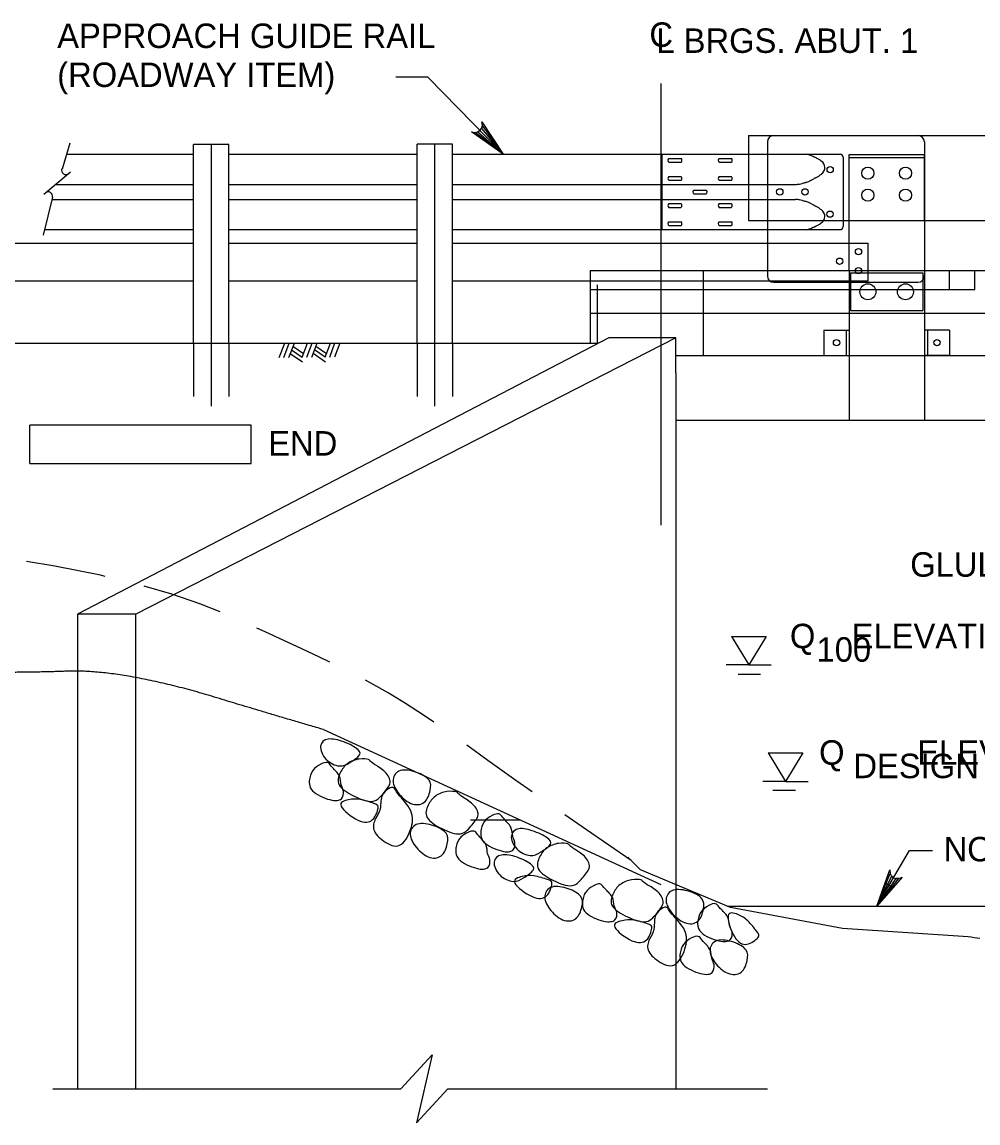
# Model space of a CAD drawing. Extents: x 638268 to 640277, y 295465 to 298435.
# Drawn here: x 638488.1 to 638605.4, y 297978 to 298112.9 of the extents above; entities that cross this region are included whole.
import ezdxf

# ---------------------------------------------------------------- set-up
doc = ezdxf.new("R2010")
doc.units = 0
for name, color, linetype in [('2', 7, 'Continuous'), ('3', 7, 'Continuous'), ('4', 7, 'Continuous'), ('52', 7, 'Continuous'), ('8', 7, 'Continuous'), ('Level 25', 7, 'Continuous')]:
    doc.layers.add(name, color=color, linetype=linetype)

msp = doc.modelspace()

# ---------------------------------------------------------------- linework, layer by layer
at = {"layer": '2'}
for p, q in [((638577.23, 298099.02), (638577.23, 298096.71)), ((638577.23, 298099.02), (638750.23, 298099.02)), ((638493.6, 298096.72), (638509.18, 298096.72)), ((638513.5, 298096.72), (638536.57, 298096.72)), ((638540.9, 298096.72), (638566.58, 298096.72)), ((638566.58, 298096.72), (638566.58, 298087.48)), ((638566.64, 298096.72), (638577.23, 298096.72)), ((638577.23, 298096.72), (638588.44, 298096.72)), ((638577.23, 298096.7), (638577.23, 298088.62)), ((638589.55, 298096.7), (638598.78, 298096.7)), ((638589.55, 298082.46), (638589.55, 298096.7)), ((638598.78, 298088.62), (638598.78, 298096.7)), ((638567.45, 298096.21), (638568.92, 298096.21)), ((638567.45, 298095.75), (638568.92, 298095.75)), ((638573.62, 298096.21), (638575.1, 298096.21)), ((638573.62, 298095.75), (638575.1, 298095.75)), ((638588.81, 298096.35), (638588.81, 298087.85)), ((638589.55, 298096.32), (638598.78, 298096.32)), ((638567.45, 298093.99), (638568.92, 298093.99)), ((638573.62, 298093.99), (638575.1, 298093.99)), ((638492.25, 298093.02), (638509.18, 298093.02)), ((638513.5, 298093.02), (638536.57, 298093.02)), ((638540.9, 298093.02), (638577.23, 298093.02)), ((638567.45, 298093.53), (638568.92, 298093.53)), ((638570.53, 298092.33), (638572.01, 298092.33)), ((638573.62, 298093.53), (638575.1, 298093.53)), ((638577.23, 298093.02), (638582.98, 298093.02)), ((638491.81, 298091.18), (638509.18, 298091.18)), ((638513.5, 298091.18), (638536.57, 298091.18)), ((638540.9, 298091.18), (638577.23, 298091.18)), ((638570.53, 298091.87), (638572.01, 298091.87)), ((638577.23, 298091.18), (638582.98, 298091.18)), ((638567.45, 298090.67), (638568.92, 298090.67)), ((638567.45, 298090.2), (638568.92, 298090.2)), ((638573.62, 298090.67), (638575.1, 298090.67)), ((638573.62, 298090.2), (638575.1, 298090.2)), ((638567.45, 298088.45), (638568.92, 298088.45)), ((638573.62, 298088.45), (638575.1, 298088.45)), ((638577.23, 298088.62), (638579.54, 298088.62)), ((638579.54, 298088.62), (638589.55, 298088.62)), ((638589.55, 298088.62), (638598.78, 298088.62)), ((638598.78, 298088.62), (638598.78, 298082.46)), ((638598.78, 298088.62), (638637.2, 298088.62)), ((638490.88, 298087.48), (638509.18, 298087.48)), ((638513.5, 298087.48), (638536.57, 298087.48)), ((638540.9, 298087.48), (638579.54, 298087.48)), ((638567.45, 298087.99), (638568.92, 298087.99)), ((638573.62, 298087.99), (638575.1, 298087.99)), ((638579.54, 298087.48), (638588.44, 298087.48)), ((638486.95, 298085.82), (638509.18, 298085.82)), ((638513.5, 298085.82), (638536.57, 298085.82)), ((638540.9, 298085.82), (638579.54, 298085.82)), ((638579.54, 298085.82), (638591.89, 298085.82)), ((638591.89, 298081.2), (638591.89, 298085.82)), ((638557.8, 298082.46), (638589.55, 298082.46)), ((638557.8, 298082.46), (638557.8, 298073.51)), ((638571.65, 298082.46), (638571.65, 298072.07)), ((638579.54, 298082.46), (638579.54, 298081.8)), ((638589.55, 298082.46), (638598.78, 298082.46)), ((638589.55, 298082.46), (638589.55, 298064.14)), ((638589.71, 298082.18), (638589.71, 298077.56)), ((638589.71, 298082.18), (638598.59, 298082.18)), ((638598.59, 298082.18), (638598.59, 298077.56)), ((638598.78, 298082.46), (638637.2, 298082.46)), ((638598.78, 298082.46), (638598.78, 298064.14)), ((638601.86, 298080.15), (638601.86, 298082.46)), ((638604.95, 298080.15), (638604.95, 298082.46)), ((638485.55, 298081.2), (638509.18, 298081.2)), ((638513.5, 298081.2), (638536.57, 298081.2)), ((638540.9, 298081.2), (638557.8, 298081.2)), ((638557.8, 298081.2), (638591.89, 298081.2)), ((638557.8, 298080.15), (638604.95, 298080.15)), ((638589.71, 298077.56), (638598.59, 298077.56)), ((638557.8, 298077.26), (638589.55, 298077.26)), ((638589.55, 298077.26), (638598.78, 298077.26)), ((638598.78, 298077.26), (638614.94, 298077.26)), ((638586.45, 298075.16), (638589.55, 298075.16)), ((638586.45, 298075.16), (638586.45, 298072.07)), ((638589.18, 298075.16), (638589.18, 298072.07)), ((638589.55, 298075.16), (638589.55, 298072.07)), ((638601.87, 298075.16), (638598.78, 298075.16)), ((638598.78, 298075.16), (638598.78, 298072.07)), ((638599.15, 298075.16), (638599.15, 298072.07)), ((638601.87, 298075.16), (638601.87, 298072.07)), ((638586.45, 298072.07), (638589.55, 298072.07)), ((638589.55, 298072.07), (638598.78, 298072.07)), ((638601.87, 298072.07), (638598.78, 298072.07)), ((638598.78, 298072.07), (638637.2, 298072.07)), ((638601.87, 298072.07), (638598.78, 298072.07))]:
    msp.add_line(p, q, dxfattribs=at)
for centre, radius in [((638587.23, 298094.84), 0.385), ((638591.85, 298094.4), 0.748), ((638596.47, 298094.4), 0.748), ((638581.05, 298092.11), 0.385), ((638584.13, 298092.11), 0.385), ((638591.85, 298091.7), 0.748), ((638596.47, 298091.7), 0.748), ((638587.21, 298089.38), 0.385), ((638590.7, 298084.77), 0.385), ((638588.39, 298083.61), 0.385), ((638590.7, 298082.46), 0.385), ((638591.85, 298079.86), 0.978), ((638596.46, 298079.86), 0.978), ((638588.01, 298073.62), 0.385), ((638600.32, 298073.62), 0.385)]:
    msp.add_circle(centre, radius, dxfattribs=at)
for centre, radius, start, end in [((638581.4, 298086.99), 10.17, 71.5066, 72.9766), ((638584.03, 298094.85), 1.88, 68.0907, 71.5066), ((638560.58, 298036.55), 64.73, 67.6851, 68.0907), ((638582.91, 298090.94), 5.93, 66.3453, 67.6851), ((638584.32, 298094.16), 2.42, 63.4251, 66.3453), ((638588.44, 298096.35), 0.369, 0, 90), ((638567.58, 298095.98), 0.269, 120.8559, 239.1441), ((638568.79, 298095.98), 0.269, 300.8559, 59.1441), ((638573.76, 298095.98), 0.269, 120.8559, 239.1441), ((638574.96, 298095.98), 0.269, 300.8559, 59.1441), ((638571.17, 298067.88), 31.8, 62.6202, 63.4251), ((638585.36, 298095.27), 0.955, 54.6771, 62.6202), ((638583.36, 298092.45), 4.42, 50.9849, 54.6771), ((638585.67, 298095.09), 0.916, 301.3851, 59.6468), ((638567.58, 298093.76), 0.269, 120.8559, 239.1441), ((638568.79, 298093.76), 0.269, 300.8559, 59.1441), ((638573.76, 298093.76), 0.269, 120.8559, 239.1441), ((638574.96, 298093.76), 0.269, 300.8559, 59.1441), ((638640.28, 297992.66), 115.08, 118.565, 118.7501), ((638645.68, 297982.76), 126.36, 118.4725, 118.565), ((638398.16, 298439.15), 392.83, 298.4725, 298.525), ((638585.23, 298094.96), 1.09, 298.525, 306.8818), ((638582.92, 298098.04), 4.94, 306.8818, 310.7993), ((638570.66, 298092.1), 0.269, 120.8559, 239.1441), ((638571.87, 298092.1), 0.269, 300.8559, 59.1441), ((638582.75, 298098.05), 5.03, 272.6429, 278.367), ((638583.16, 298095.21), 2.16, 278.367, 287.1115), ((638556.74, 298181.03), 91.96, 287.1115, 287.3611), ((638583.24, 298096.26), 3.14, 287.3611, 288.7111), ((638578.42, 298110.5), 18.18, 288.7111, 290.2329), ((638584.49, 298094.05), 0.644, 290.2329, 298.3215), ((638574.61, 298112.37), 21.45, 298.3215, 298.7501), ((638582.75, 298086.15), 5.03, 81.633, 87.3571), ((638583.16, 298088.99), 2.16, 72.8885, 81.633), ((638556.74, 298003.16), 91.96, 72.6389, 72.8885), ((638567.58, 298090.44), 0.269, 120.8559, 239.1441), ((638568.79, 298090.44), 0.269, 300.8559, 59.1441), ((638573.76, 298090.44), 0.269, 120.8559, 239.1441), ((638574.96, 298090.44), 0.269, 300.8559, 59.1441), ((638583.24, 298087.94), 3.14, 71.2889, 72.6389), ((638578.42, 298073.7), 18.18, 69.7671, 71.2889), ((638584.49, 298090.15), 0.644, 61.6785, 69.7671), ((638574.61, 298071.83), 21.45, 61.2499, 61.6785), ((638640.28, 298191.53), 115.08, 241.2499, 241.435), ((638645.68, 298201.44), 126.36, 241.435, 241.5275), ((638398.16, 297745.04), 392.83, 61.475, 61.5275), ((638585.23, 298089.23), 1.09, 53.1182, 61.475), ((638582.92, 298086.15), 4.94, 49.2007, 53.1182), ((638585.67, 298089.11), 0.916, 300.3532, 58.6149), ((638567.58, 298088.22), 0.269, 120.8559, 239.1441), ((638568.79, 298088.22), 0.269, 300.8559, 59.1441), ((638573.76, 298088.22), 0.269, 120.8559, 239.1441), ((638574.96, 298088.22), 0.269, 300.8559, 59.1441), ((638583.36, 298091.75), 4.42, 305.3229, 309.0151), ((638581.4, 298097.2), 10.17, 287.0234, 288.4934), ((638584.03, 298089.35), 1.88, 288.4934, 291.9093), ((638560.58, 298147.65), 64.73, 291.9093, 292.3149), ((638582.91, 298093.26), 5.93, 292.3149, 293.6547), ((638584.32, 298090.04), 2.42, 293.6547, 296.5749), ((638571.17, 298116.32), 31.8, 296.5749, 297.3798), ((638585.36, 298088.93), 0.955, 297.3798, 305.3229), ((638588.44, 298087.85), 0.369, 270, 0)]:
    msp.add_arc(centre, radius, start, end, dxfattribs=at)
at = {"layer": '3'}
for p, q in [((638513.5, 298097.9), (638509.18, 298097.9)), ((638509.18, 298073.51), (638509.18, 298097.9)), ((638511.34, 298097.9), (638511.34, 298065.82)), ((638513.5, 298073.51), (638513.5, 298097.9)), ((638540.9, 298097.98), (638536.57, 298097.98)), ((638536.57, 298073.51), (638536.57, 298097.98)), ((638538.73, 298097.98), (638538.73, 298065.82)), ((638540.9, 298073.51), (638540.9, 298097.98)), ((638494.06, 298094.54), (638490.8, 298091.8)), ((638491.88, 298091.46), (638490.71, 298086.79)), ((638558.69, 298073.51), (638558.69, 298080.72)), ((638558.69, 298073.51), (638480.78, 298073.51)), ((638558.69, 298073.51), (638493.49, 298073.51)), ((638560.07, 298074.23), (638494.94, 298040.35)), ((638568.29, 298074.23), (638502.08, 298040.35)), ((638509.18, 298073.51), (638509.18, 298067.03)), ((638513.5, 298073.51), (638513.5, 298067.03)), ((638520.3, 298073.51), (638519.64, 298071.76)), ((638520.3, 298073.51), (638519.64, 298071.76)), ((638520.85, 298073.52), (638520.18, 298071.76)), ((638520.85, 298073.52), (638520.18, 298071.76)), ((638521.49, 298073.53), (638520.82, 298071.78)), ((638521.49, 298073.53), (638520.82, 298071.78)), ((638523.11, 298073.53), (638522.46, 298071.8)), ((638523.11, 298073.53), (638522.46, 298071.8)), ((638523.66, 298073.54), (638523.01, 298071.81)), ((638523.66, 298073.54), (638523.01, 298071.81)), ((638524.3, 298073.54), (638523.64, 298071.82)), ((638524.3, 298073.54), (638523.64, 298071.82)), ((638525.92, 298073.54), (638525.27, 298071.81)), ((638525.92, 298073.54), (638525.27, 298071.81)), ((638526.47, 298073.55), (638525.82, 298071.82)), ((638526.47, 298073.55), (638525.82, 298071.82)), ((638527.11, 298073.55), (638526.45, 298071.83)), ((638527.11, 298073.55), (638526.45, 298071.83)), ((638536.57, 298073.51), (638536.57, 298067.03)), ((638540.9, 298073.51), (638540.9, 298067.03)), ((638568.29, 298074.23), (638560.07, 298074.23)), ((638568.29, 298069.91), (638568.29, 298074.23)), ((638521.02, 298072.31), (638522.52, 298071.27)), ((638521.02, 298072.31), (638522.52, 298071.27)), ((638521.19, 298072.76), (638522.48, 298071.86)), ((638521.19, 298072.76), (638522.48, 298071.86)), ((638521.35, 298073.19), (638522.64, 298072.29)), ((638521.35, 298073.19), (638522.64, 298072.29)), ((638523.83, 298072.32), (638525.33, 298071.28)), ((638523.83, 298072.32), (638525.33, 298071.28)), ((638524, 298072.77), (638525.29, 298071.88)), ((638524, 298072.77), (638525.29, 298071.88)), ((638524.16, 298073.2), (638525.45, 298072.3)), ((638524.16, 298073.2), (638525.45, 298072.3)), ((638568.29, 298072.07), (638589.55, 298072.07)), ((638568.29, 298069.91), (638568.29, 298007.18)), ((638568.29, 298064.14), (638747.07, 298064.14)), ((638502.08, 298040.35), (638494.94, 298040.35)), ((638494.94, 298040.35), (638494.94, 298033.23)), ((638502.08, 298032.48), (638502.08, 298040.35)), ((638494.94, 298033.23), (638494.94, 297982.13)), ((638502.08, 297982.13), (638502.08, 298032.48)), ((638525.11, 298026.19), (638566.48, 298007.21)), ((638543.13, 298015.12), (638549.23, 298015.12)), ((638568.29, 298007.18), (638568.29, 297982.13)), ((638574.64, 298004.52), (638735.37, 298004.52)), ((638534.59, 297982.13), (638538.43, 297986.3)), ((638538.43, 297986.3), (638536.51, 297977.96)), ((638491.9, 297982.13), (638534.59, 297982.13)), ((638536.51, 297977.96), (638540.35, 297982.13)), ((638540.35, 297982.13), (638579.55, 297982.13))]:
    msp.add_line(p, q, dxfattribs=at)
for centre, radius, start, end in [((638493.5, 298094.77), 0.533, 162.1496, 312.1496), ((638491.36, 298091.58), 0.533, 130.0028, 130.0168), ((638491.36, 298091.58), 0.533, 347.4782, 130.0168), ((638613.42, 298071.3), 71.1, 262.5202, 263.6598)]:
    msp.add_arc(centre, radius, start, end, dxfattribs=at)
for points, degree in [([(638525.11, 298026.19), (638516.58, 298028.68), (638506.65, 298031.73), (638497.12, 298033.48), (638489.77, 298033.19), (638483.62, 298033.19)], 2), ([(638529.39, 298022.92), (638529.15, 298022.66), (638528.28, 298022.11), (638527.18, 298021.46), (638525.2, 298022.4), (638524.44, 298024.33), (638525.52, 298025.24), (638527.55, 298024.8), (638529.73, 298023.65), (638529.63, 298023.18), (638529.39, 298022.92)], 3), ([(638527.27, 298019.42), (638527.34, 298019.12), (638527.64, 298018.75), (638527.49, 298017.53), (638526.14, 298017.36), (638523.25, 298018.61), (638523.34, 298020.36), (638523.86, 298021.47), (638525.12, 298022.17), (638525.77, 298022.2), (638526.07, 298021.59), (638527.24, 298020.56), (638527.2, 298019.72), (638527.27, 298019.42)], 3), ([(638530.8, 298022.36), (638530.86, 298022.28), (638531.19, 298021.99), (638532.78, 298021.07), (638533.57, 298019.64), (638532.57, 298018.59), (638531.37, 298016.96), (638528.79, 298017.96), (638526.57, 298019.38), (638527.12, 298020.98), (638527.91, 298022.1), (638529.51, 298022.71), (638530.86, 298022.5), (638530.75, 298022.45), (638530.8, 298022.36)], 3), ([(638538.03, 298020.02), (638538.31, 298019.65), (638538.27, 298018.81), (638537.65, 298016.99), (638535.8, 298016.85), (638534.06, 298018.47), (638533.36, 298020.11), (638534.33, 298021.45), (638536.6, 298021.04), (638537.75, 298020.39), (638538.03, 298020.02)], 3), ([(638533.71, 298019.05), (638533.85, 298018.96), (638533.96, 298018.51), (638536.22, 298016.2), (638535.97, 298013.99), (638534.57, 298011.4), (638532.38, 298012.41), (638530.96, 298013.92), (638531.44, 298015.29), (638532.19, 298016.31), (638532.04, 298018.14), (638533.13, 298019.05), (638533.57, 298019.14), (638533.71, 298019.05)], 3), ([(638541.58, 298018.38), (638541.64, 298018.3), (638541.97, 298018.01), (638543.55, 298017.09), (638544.35, 298015.66), (638543.35, 298014.61), (638542.14, 298012.98), (638539.56, 298013.98), (638537.34, 298015.39), (638537.89, 298016.99), (638538.68, 298018.12), (638540.28, 298018.73), (638541.63, 298018.52), (638541.52, 298018.46), (638541.58, 298018.38)], 3), ([(638531.26, 298017.14), (638531.68, 298016.99), (638531.99, 298016.89), (638531.28, 298014.83), (638529.56, 298014.66), (638526.44, 298017.12), (638528.28, 298017.65), (638529.47, 298017.75), (638530.84, 298017.28), (638531.26, 298017.14)], 3), ([(638548.3, 298013.13), (638548.36, 298012.83), (638548.66, 298012.46), (638548.51, 298011.24), (638547.17, 298011.07), (638544.27, 298012.32), (638544.37, 298014.07), (638544.88, 298015.17), (638546.14, 298015.88), (638546.8, 298015.91), (638547.09, 298015.3), (638548.27, 298014.26), (638548.23, 298013.43), (638548.3, 298013.13)], 3), ([(638540.14, 298013.47), (638540.41, 298013.1), (638540.38, 298012.26), (638539.75, 298010.44), (638537.91, 298010.3), (638536.16, 298011.92), (638535.46, 298013.56), (638536.43, 298014.9), (638538.7, 298014.49), (638539.86, 298013.84), (638540.14, 298013.47)], 3), ([(638552.78, 298011.94), (638552.54, 298011.68), (638551.67, 298011.13), (638550.57, 298010.48), (638548.59, 298011.42), (638547.83, 298013.35), (638548.91, 298014.25), (638550.94, 298013.81), (638553.12, 298012.67), (638553.02, 298012.19), (638552.78, 298011.94)], 3), ([(638545.23, 298011.01), (638545.3, 298010.71), (638545.6, 298010.34), (638545.45, 298009.11), (638544.1, 298008.95), (638541.21, 298010.2), (638541.3, 298011.95), (638541.81, 298013.05), (638543.07, 298013.76), (638543.73, 298013.79), (638544.03, 298013.18), (638545.2, 298012.15), (638545.16, 298011.31), (638545.23, 298011.01)], 3), ([(638555.25, 298012.02), (638555.3, 298011.94), (638555.63, 298011.65), (638557.22, 298010.74), (638558.01, 298009.3), (638557.01, 298008.25), (638555.81, 298006.62), (638553.23, 298007.63), (638551.01, 298009.04), (638551.56, 298010.64), (638552.35, 298011.76), (638553.95, 298012.37), (638555.3, 298012.16), (638555.19, 298012.11), (638555.25, 298012.02)], 3), ([(638550.7, 298008.82), (638550.46, 298008.55), (638549.61, 298007.98), (638548.52, 298007.31), (638546.52, 298008.19), (638545.71, 298010.1), (638546.77, 298011.03), (638548.8, 298010.65), (638551.01, 298009.56), (638550.93, 298009.08), (638550.7, 298008.82)], 3), ([(638552.56, 298007.81), (638552.98, 298007.67), (638553.29, 298007.58), (638552.64, 298005.5), (638550.92, 298005.28), (638547.74, 298007.67), (638549.56, 298008.24), (638550.75, 298008.38), (638552.14, 298007.94), (638552.56, 298007.81)], 3), ([(638560.76, 298004.57), (638560.84, 298004.28), (638561.15, 298003.92), (638561.03, 298002.69), (638559.69, 298002.49), (638556.77, 298003.66), (638556.81, 298005.42), (638557.3, 298006.53), (638558.54, 298007.27), (638559.19, 298007.32), (638559.51, 298006.71), (638560.71, 298005.71), (638560.69, 298004.87), (638560.76, 298004.57)], 3), ([(638564.22, 298007.61), (638564.28, 298007.52), (638564.62, 298007.25), (638566.23, 298006.37), (638567.06, 298004.96), (638566.08, 298003.88), (638564.92, 298002.22), (638562.32, 298003.16), (638560.06, 298004.51), (638560.57, 298006.13), (638561.33, 298007.27), (638562.92, 298007.92), (638564.27, 298007.75), (638564.16, 298007.69), (638564.22, 298007.61)], 3), ([(638556.63, 298005.76), (638556.91, 298005.39), (638556.87, 298004.55), (638556.24, 298002.72), (638554.4, 298002.59), (638552.65, 298004.21), (638551.96, 298005.84), (638552.92, 298007.18), (638555.2, 298006.77), (638556.35, 298006.13), (638556.63, 298005.76)], 3), ([(638571.51, 298005.45), (638571.8, 298005.09), (638571.78, 298004.25), (638571.2, 298002.41), (638569.36, 298002.23), (638567.57, 298003.8), (638566.83, 298005.42), (638567.77, 298006.78), (638570.05, 298006.43), (638571.22, 298005.82), (638571.51, 298005.45)], 3), ([(638574.9, 298002.16), (638574.98, 298001.86), (638575.29, 298001.5), (638575.17, 298000.27), (638573.83, 298000.07), (638570.9, 298001.24), (638570.95, 298003), (638571.44, 298004.11), (638572.68, 298004.85), (638573.33, 298004.9), (638573.65, 298004.29), (638574.85, 298003.29), (638574.83, 298002.46), (638574.9, 298002.16)], 3), ([(638567.21, 298004.37), (638567.35, 298004.29), (638567.47, 298003.83), (638569.8, 298001.59), (638569.6, 297999.37), (638568.27, 297996.75), (638566.05, 297997.7), (638564.6, 297999.17), (638565.03, 298000.55), (638565.76, 298001.59), (638565.57, 298003.42), (638566.63, 298004.35), (638567.07, 298004.46), (638567.21, 298004.37)], 3), ([(638578.24, 298001.44), (638578.51, 298001.09), (638578.7, 298000.83), (638576.98, 297999.51), (638575.45, 298000.31), (638574.21, 298004.09), (638576.04, 298003.51), (638577.08, 298002.94), (638577.97, 298001.79), (638578.24, 298001.44)], 3), ([(638564.81, 298002.39), (638565.24, 298002.26), (638565.54, 298002.16), (638564.89, 298000.09), (638563.17, 297999.87), (638559.99, 298002.26), (638561.82, 298002.83), (638563, 298002.96), (638564.39, 298002.53), (638564.81, 298002.39)], 3), ([(638572.72, 297998.11), (638572.79, 297997.81), (638573.09, 297997.44), (638572.94, 297996.22), (638571.59, 297996.05), (638568.7, 297997.3), (638568.79, 297999.06), (638569.31, 298000.16), (638570.57, 298000.86), (638571.22, 298000.89), (638571.52, 298000.28), (638572.69, 297999.25), (638572.65, 297998.41), (638572.72, 297998.11)], 3), ([(638576.89, 297999.19), (638577.17, 297998.82), (638577.14, 297997.98), (638576.51, 297996.16), (638574.67, 297996.02), (638572.92, 297997.64), (638572.22, 297999.28), (638573.19, 298000.62), (638575.46, 298000.21), (638576.62, 297999.56), (638576.89, 297999.19)], 3)]:
    msp.add_open_spline(points, degree=degree, dxfattribs=at)
at = {"layer": '4'}
for p, q in [((638537.91, 298106.18), (638533.97, 298106.18)), ((638547.12, 298096.72), (638537.91, 298106.18)), ((638566.48, 298105.41), (638566.48, 298051.26)), ((638516.23, 298063.5), (638489.08, 298063.5)), ((638489.08, 298058.79), (638489.08, 298063.5)), ((638516.23, 298058.79), (638516.23, 298063.5)), ((638489.08, 298058.79), (638516.23, 298058.79)), ((638575.12, 298037.61), (638577.24, 298034.12)), ((638575.12, 298037.61), (638579.36, 298037.61)), ((638579.36, 298037.61), (638577.24, 298034.12)), ((638577.24, 298034.12), (638574.47, 298034.12)), ((638575.93, 298032.98), (638578.7, 298032.98)), ((638577.24, 298034.12), (638580.01, 298034.12)), ((638579.64, 298023.33), (638583.88, 298023.33)), ((638579.64, 298023.33), (638581.76, 298019.84)), ((638583.88, 298023.33), (638581.76, 298019.84)), ((638581.76, 298019.84), (638578.99, 298019.84)), ((638581.76, 298019.84), (638584.53, 298019.84)), ((638580.2, 298018.76), (638582.97, 298018.76)), ((638592.94, 298004.52), (638596.95, 298011.38)), ((638596.95, 298011.38), (638599.76, 298011.38))]:
    msp.add_line(p, q, dxfattribs=at)
for points in [[(638547.12, 298096.72), (638543.25, 298099.46), (638543.68, 298099.38), (638544.03, 298099.46), (638544.29, 298099.64), (638544.48, 298099.9), (638544.58, 298100.25), (638544.51, 298100.68), (638547.12, 298096.72), (638544.58, 298100.25), (638544.48, 298099.9), (638547.12, 298096.72), (638544.29, 298099.64), (638544.03, 298099.46), (638547.12, 298096.72), (638543.68, 298099.38)], [(638604.16, 298000.8), (638588.76, 298001.8), (638575.01, 298004.37), (638563.97, 298008.99), (638562.4, 298010.55)], [(638592.94, 298004.52), (638594.54, 298008.99), (638594.57, 298008.55), (638594.75, 298008.23), (638594.99, 298008.03), (638595.29, 298007.92), (638595.65, 298007.92), (638596.05, 298008.1), (638592.94, 298004.52), (638595.65, 298007.92), (638595.29, 298007.92), (638592.94, 298004.52), (638594.99, 298008.03), (638594.75, 298008.23), (638592.94, 298004.52), (638594.57, 298008.55)]]:
    msp.add_lwpolyline(points, dxfattribs=at)
msp.add_lwpolyline([(638594.05, 298007.36), (638594.87, 298006.88), (638593, 298004.64)], close=True, dxfattribs=at)
at = {"layer": '52'}
msp.add_line((638494.01, 298098.08), (638493.07, 298094.91), dxfattribs=at)
at = {"layer": '8'}
for p, q in [((638492.15, 298046.23), (638488.69, 298046.8)), ((638497.74, 298045.11), (638492.15, 298046.23)), ((638498.35, 298044.96), (638497.74, 298045.11)), ((638506.51, 298042.78), (638503.12, 298043.77)), ((638509.95, 298041.59), (638506.51, 298042.78)), ((638512.44, 298040.61), (638509.95, 298041.59)), ((638517.95, 298038.16), (638516.94, 298038.62)), ((638520.25, 298037.1), (638517.95, 298038.16)), ((638522.46, 298036.08), (638520.25, 298037.1)), ((638524.62, 298035.06), (638522.46, 298036.08)), ((638525.86, 298034.46), (638524.62, 298035.06)), ((638530.92, 298031.87), (638530.25, 298032.23)), ((638533.02, 298030.68), (638530.92, 298031.87)), ((638535.16, 298029.38), (638533.02, 298030.68)), ((638537.35, 298027.95), (638535.16, 298029.38)), ((638538.63, 298027.08), (638537.35, 298027.95)), ((638545.26, 298022.41), (638542.66, 298024.26)), ((638548.69, 298019.96), (638545.26, 298022.41)), ((638550.69, 298018.56), (638548.69, 298019.96)), ((638557.36, 298013.88), (638554.71, 298015.73)), ((638562.81, 298010.14), (638557.36, 298013.88))]:
    msp.add_line(p, q, dxfattribs=at)
at = {"layer": 'Level 25'}
for p, q in [((638579.54, 298098.25), (638579.54, 298096.71)), ((638580.31, 298099.02), (638598.01, 298099.02)), ((638598.78, 298098.25), (638598.78, 298096.7)), ((638579.54, 298096.71), (638579.54, 298087.47)), ((638598.78, 298096.7), (638598.78, 298081.8)), ((638579.54, 298087.47), (638579.54, 298082.46)), ((638580.31, 298081.03), (638598.01, 298081.03))]:
    msp.add_line(p, q, dxfattribs=at)
for centre, start, end in [((638580.31, 298098.25), 90, 180), ((638598.01, 298098.25), 0, 90), ((638580.31, 298081.8), 180, 270), ((638598.01, 298081.8), 270, 0)]:
    msp.add_arc(centre, 0.77, start, end, dxfattribs=at)

# ---------------------------------------------------------------- texts
at = {"layer": '4'}
for s, p in [('APPROACH GUIDE RAIL', (638492.45, 298109.75)), ('C', (638565.06, 298109.89)), ('L BRGS. ABUT. 1', (638565.92, 298109.15)), ('(ROADWAY ITEM)', (638492.45, 298104.97)), ('END', (638518.33, 298059.78)), ('GLULAM STIFFENER BEAM (TYP.)', (638597.04, 298044.93)), ('Q    ELEVATION - ', (638582.29, 298036.16)), ('100', (638585.56, 298034.51)), ('Q        ELEVATION - ', (638585.87, 298021.88)), ('DESIGN', (638590.08, 298020.23)), ('NORMAL WATER ELEV. -', (638601.14, 298010.03))]:
    msp.add_text(s, height=3, dxfattribs=at).set_placement(p)

doc.saveas('drawing.dxf')
